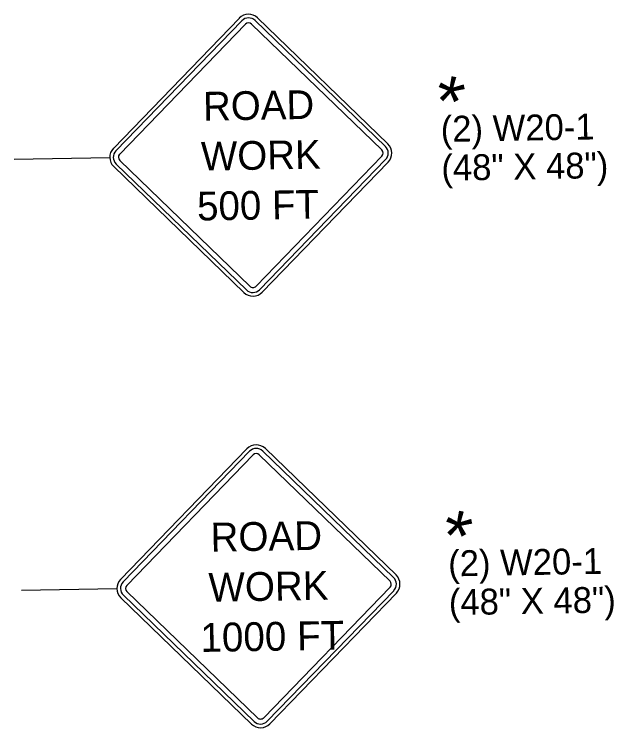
# Model space of a CAD drawing. Extents: x 1676063 to 1678026, y 228339 to 229904.
# Drawn here: x 1677194.8 to 1677333.8, y 228745.9 to 228911.5 of the extents above; entities that cross this region are included whole.
import ezdxf

# ---------------------------------------------------------------- set-up
doc = ezdxf.new("R2010")
doc.units = 0
for name, color, linetype in [('P_TC_Signs_Temporary', 7, 'Continuous'), ('R_Annotation', 7, 'Continuous'), ('R_Draft', 7, 'Continuous')]:
    doc.layers.add(name, color=color, linetype=linetype)

msp = doc.modelspace()

# ---------------------------------------------------------------- linework, layer by layer
at = {"layer": 'P_TC_Signs_Temporary'}
for p, q in [((1677251.21, 228910.62), (1677281.4, 228881.42)), ((1677217.76, 228880.36), (1677246.97, 228910.55)), ((1677218.36, 228879.78), (1677247.57, 228909.97)), ((1677219.2, 228878.97), (1677248.4, 228909.16)), ((1677249.82, 228909.18), (1677280, 228879.98)), ((1677250.63, 228910.02), (1677280.82, 228880.82)), ((1677249.41, 228848.36), (1677219.23, 228877.56)), ((1677280.03, 228878.57), (1677250.83, 228848.38)), ((1677280.87, 228877.76), (1677251.66, 228847.57)), ((1677248.02, 228846.92), (1677217.84, 228876.12)), ((1677248.6, 228847.52), (1677218.41, 228876.72)), ((1677281.47, 228877.18), (1677252.26, 228846.99)), ((1677219.43, 228780.36), (1677248.74, 228810.66)), ((1677220.03, 228779.78), (1677249.34, 228810.08)), ((1677252.41, 228810.13), (1677282.71, 228780.82)), ((1677253, 228810.73), (1677283.3, 228781.42)), ((1677220.87, 228778.97), (1677250.18, 228809.27)), ((1677251.6, 228809.29), (1677281.9, 228779.98)), ((1677281.92, 228778.56), (1677252.61, 228748.26)), ((1677250.38, 228747.39), (1677220.08, 228776.71)), ((1677251.19, 228748.24), (1677220.89, 228777.55)), ((1677282.76, 228777.74), (1677253.45, 228747.45)), ((1677283.37, 228777.16), (1677254.05, 228746.86)), ((1677249.8, 228746.79), (1677219.5, 228776.1))]:
    msp.add_line(p, q, dxfattribs=at)
for centre, radius, start, end in [((1677249.12, 228908.46), 3, 45.9497, 135.9497), ((1677249.12, 228908.46), 2.17, 45.9497, 135.9497), ((1677249.12, 228908.46), 1, 45.9497, 135.9497), ((1677279.31, 228879.26), 2.17, 315.9497, 45.9497), ((1677279.31, 228879.26), 3, 315.9497, 45.9497), ((1677219.92, 228878.28), 3, 135.9497, 225.9497), ((1677219.92, 228878.28), 2.17, 135.9497, 225.9497), ((1677279.31, 228879.26), 1, 315.9497, 45.9497), ((1677219.92, 228878.28), 1, 135.9497, 225.9497), ((1677250.11, 228849.08), 1, 225.9497, 315.9497), ((1677250.11, 228849.08), 3, 225.9497, 315.9497), ((1677250.11, 228849.08), 2.17, 225.9497, 315.9497), ((1677250.9, 228808.57), 3.01, 45.9497, 135.9497), ((1677250.9, 228808.57), 2.17, 45.9497, 135.9497), ((1677250.9, 228808.57), 1, 45.9497, 135.9497), ((1677221.59, 228778.27), 3.01, 135.9497, 225.9497), ((1677281.2, 228779.26), 1, 315.9497, 45.9497), ((1677281.2, 228779.26), 2.17, 315.9497, 45.9497), ((1677281.2, 228779.26), 3.01, 315.9497, 45.9497), ((1677221.59, 228778.27), 2.17, 135.9497, 225.9497), ((1677221.59, 228778.27), 1, 135.9497, 225.9497), ((1677251.89, 228748.96), 3.01, 225.9497, 315.9497), ((1677251.89, 228748.96), 2.17, 225.9497, 315.9497), ((1677251.89, 228748.96), 1, 225.9497, 315.9497)]:
    msp.add_arc(centre, radius, start, end, dxfattribs=at)
at = {"layer": 'R_Draft'}
for p, q in [((1677194.79, 228877.86), (1677216.92, 228878.23)), ((1677196.45, 228777.85), (1677218.58, 228778.22))]:
    msp.add_line(p, q, dxfattribs=at)

# ---------------------------------------------------------------- texts
at = {"layer": 'P_TC_Signs_Temporary'}
for s, height, p in [(' ROAD ', 6.667, (1677236.13, 228886.74)), ('WORK', 6.667, (1677238.13, 228875.19)), ('500 FT ', 6.667, (1677237.23, 228863.6)), (' ROAD ', 6.692, (1677237.86, 228786.76)), ('WORK', 6.692, (1677239.86, 228775.17)), ('1000 FT', 6.692, (1677238, 228763.52))]:
    msp.add_text(s, height=height, rotation=0.9497, dxfattribs=at).set_placement(p)
at = {"layer": 'R_Annotation'}
for s, height, rotation, p in [('*', 12, 135.9497, (1677304.44, 228898.11)), ('(2) W20-1', 6, 0.9497, (1677293.7, 228881.84)), ('(48" X 48")', 6, 0.9497, (1677293.85, 228872.84)), ('*', 12, 135.9497, (1677306.17, 228797.31)), ('(2) W20-1', 6, 0.9497, (1677295.43, 228781.05)), ('(48" X 48")', 6, 0.9497, (1677295.58, 228772.05))]:
    msp.add_text(s, height=height, rotation=rotation, dxfattribs=at).set_placement(p)

doc.saveas('drawing.dxf')
